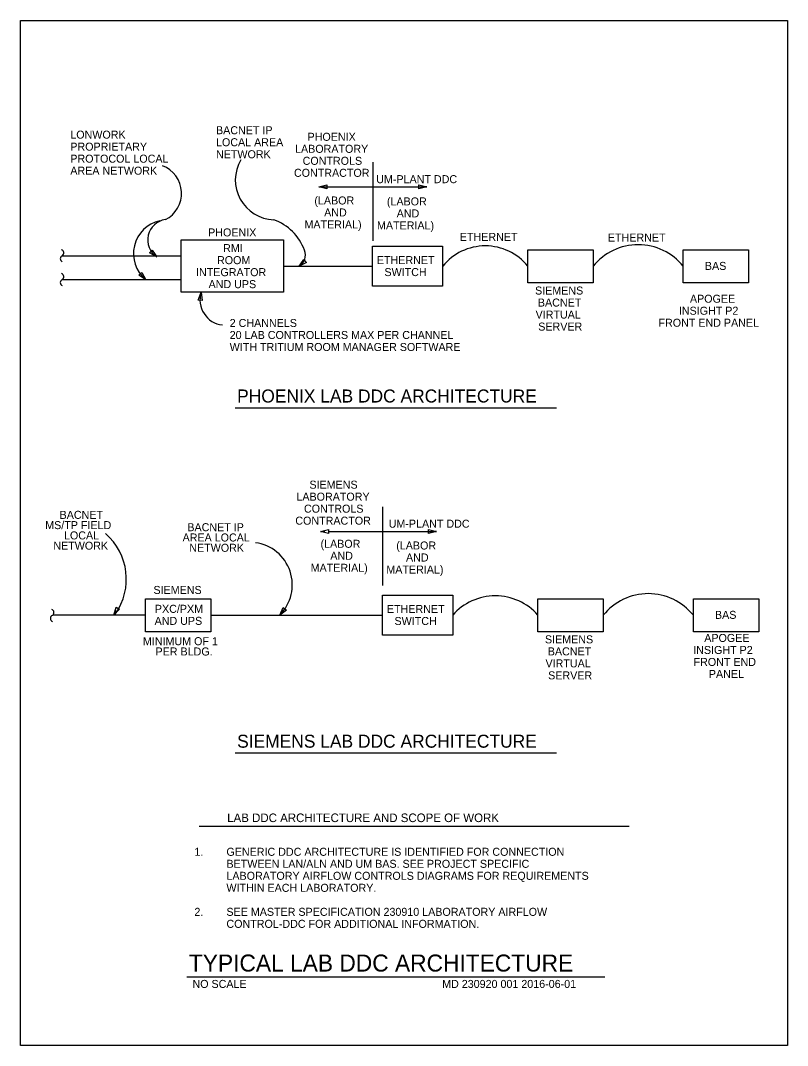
# Model space of a CAD drawing. Extents: x 10272.9 to 10336.8, y 10039.8 to 10125.2.
import ezdxf

# ---------------------------------------------------------------- set-up
doc = ezdxf.new("R2010")
doc.units = 0
for name, color, linetype in [('G-ANNO-CELL', 7, 'Continuous'), ('G-ANNO-TEXT', 7, 'Continuous'), ('G-DETL-LINE', 7, 'Continuous'), ('G-DETL-TEXT', 7, 'Continuous'), ('G-DETL-TTXT', 7, 'Continuous'), ('M-ANNO-NPLT', 7, 'Continuous'), ('M-EQPM', 7, 'Continuous')]:
    doc.layers.add(name, color=color, linetype=linetype)

msp = doc.modelspace()

# ---------------------------------------------------------------- linework, layer by layer
at = {"layer": 'G-ANNO-CELL'}
for p, q in [((10290.766, 10092.921), (10317.523, 10092.921)), ((10290.766, 10064.173), (10317.523, 10064.173)), ((10287.772, 10058.074), (10323.578, 10058.074))]:
    msp.add_line(p, q, dxfattribs=at)
at = {"layer": 'G-DETL-LINE'}
for p, q in [((10276.37, 10105.58), (10286.263, 10105.58)), ((10294.798, 10104.7), (10302.199, 10104.7)), ((10276.37, 10103.591), (10286.263, 10103.591)), ((10283.314, 10075.643), (10275.658, 10075.643)), ((10288.752, 10075.643), (10297.41, 10075.643)), ((10294.3, 10075.643), (10303.036, 10075.643))]:
    msp.add_line(p, q, dxfattribs=at)
for points in [[(10286.263, 10106.895), (10294.798, 10106.895), (10294.798, 10102.547), (10286.263, 10102.547)], [(10302.199, 10106.359), (10308.047, 10106.359), (10308.047, 10103.041), (10302.199, 10103.041)], [(10315.142, 10106.074), (10320.58, 10106.074), (10320.58, 10103.326), (10315.142, 10103.326)], [(10328.085, 10106.074), (10333.523, 10106.074), (10333.523, 10103.326), (10328.085, 10103.326)], [(10283.314, 10077.017), (10288.752, 10077.017), (10288.752, 10074.269), (10283.314, 10074.269)], [(10303.036, 10077.301), (10308.884, 10077.301), (10308.884, 10073.984), (10303.036, 10073.984)], [(10315.979, 10077.017), (10321.417, 10077.017), (10321.417, 10074.269), (10315.979, 10074.269)], [(10328.922, 10077.017), (10334.359, 10077.017), (10334.359, 10074.269), (10328.922, 10074.269)]]:
    msp.add_lwpolyline(points, close=True, dxfattribs=at)
for centre, radius, start, end in [((10276.227, 10105.814), 0.274, 301.55913, 71.51636), ((10311.595, 10101.833), 4.561, 38.93991, 141.06009), ((10324.332, 10101.668), 4.824, 38.93991, 141.06009), ((10276.474, 10105.33), 0.271, 112.5259, 247.4741), ((10276.227, 10103.825), 0.274, 301.55913, 71.51636), ((10276.474, 10103.341), 0.271, 112.5259, 247.4741), ((10312.431, 10072.53), 4.719, 41.26064, 138.73936), ((10325.169, 10072.61), 4.824, 38.93991, 141.06009), ((10275.411, 10075.858), 0.274, 301.55913, 71.51636), ((10275.659, 10075.375), 0.271, 112.5259, 247.4741)]:
    msp.add_arc(centre, radius, start, end, dxfattribs=at)
at = {"layer": 'G-DETL-TEXT'}
for p, q in [((10302.236, 10113.365), (10302.236, 10106.812)), ((10297.736, 10111.312), (10306.736, 10111.312)), ((10297.736, 10111.312), (10298.091, 10111.312)), ((10306.736, 10111.312), (10306.294, 10111.312)), ((10296.086, 10104.698), (10296.299, 10104.881)), ((10283.323, 10103.565), (10283.03, 10103.891)), ((10303.036, 10084.673), (10303.036, 10078.12)), ((10297.87, 10082.62), (10298.233, 10082.62)), ((10298.536, 10082.62), (10307.536, 10082.62)), ((10307.536, 10082.62), (10307.293, 10082.62)), ((10280.676, 10075.645), (10280.88, 10076.013)), ((10294.479, 10075.654), (10294.693, 10075.912))]:
    msp.add_line(p, q, dxfattribs=at)
for points in [[(10298.403, 10111.145), (10297.736, 10111.312), (10298.403, 10111.479)], [(10306.07, 10111.479), (10306.736, 10111.312), (10306.07, 10111.145)], [(10283.869, 10106.052), (10284.246, 10105.477), (10283.643, 10105.807)], [(10296.701, 10105.005), (10296.086, 10104.698), (10296.484, 10105.258)], [(10283.001, 10104.172), (10283.323, 10103.565), (10282.753, 10103.949)], [(10287.699, 10101.887), (10287.938, 10102.531), (10288.03, 10101.851)], [(10298.536, 10082.453), (10297.87, 10082.62), (10298.536, 10082.787)], [(10306.87, 10082.787), (10307.536, 10082.62), (10306.87, 10082.453)], [(10281.145, 10076.147), (10280.676, 10075.645), (10280.854, 10076.309)], [(10295.033, 10076.06), (10294.479, 10075.654), (10294.776, 10076.273)]]:
    msp.add_lwpolyline(points, close=True, dxfattribs=at)
for centre, radius, start, end in [((10294.11, 10111.892), 3.329, 149.90492, 267.86122), ((10283.849, 10110.774), 2.455, 296.84378, 69.20826), ((10285.096, 10105.758), 2.795, 102.39819, 230.62166), ((10285.198, 10106.894), 1.706, 98.08842, 236.10688), ((10292.589, 10104.596), 4.208, 20.03814, 70.62479), ((10295.555, 10105.627), 1.07, 299.77025, 22.59452), ((10289.936, 10101.893), 2.097, 162.28199, 263.65138), ((10276.69, 10078.643), 5.021, 324.6262, 49.2367), ((10291.983, 10078.169), 3.543, 314.77186, 82.3294)]:
    msp.add_arc(centre, radius, start, end, dxfattribs=at)
at = {"layer": 'G-DETL-TTXT'}
msp.add_line((10286.734, 10045.533), (10321.555, 10045.533), dxfattribs=at)
at = {"layer": 'M-ANNO-NPLT'}
msp.add_lwpolyline([(10272.898, 10125.166), (10336.758, 10125.166), (10336.758, 10039.806), (10272.898, 10039.806)], close=True, dxfattribs=at)

# ---------------------------------------------------------------- texts
at = {"layer": 'G-ANNO-CELL'}
for s, p in [('PHOENIX LAB DDC ARCHITECTURE', (10290.933, 10093.353)), ('SIEMENS LAB DDC ARCHITECTURE', (10290.933, 10064.606))]:
    msp.add_text(s, height=1.08333, dxfattribs=at).set_placement(p)
at = {"layer": 'G-ANNO-TEXT'}
for s, height, p in [('LONWORK ', 0.6667, (10277.044, 10115.326)), ('BACNET IP', 0.6667, (10289.176, 10115.694)), ('LOCAL AREA', 0.6667, (10289.176, 10114.694)), ('PROPRIETARY ', 0.66667, (10277.044, 10114.326)), ('NETWORK', 0.6667, (10289.176, 10113.694)), ('PROTOCOL LOCAL', 0.66667, (10277.044, 10113.326)), ('AREA NETWORK', 0.66667, (10277.044, 10112.326)), ('1.', 0.6667, (10287.377, 10055.604)), ('GENERIC DDC ARCHITECTURE IS IDENTIFIED FOR CONNECTION ', 0.66667, (10290.044, 10055.604)), ('BETWEEN LAN/ALN AND UM BAS. SEE PROJECT SPECIFIC ', 0.66667, (10290.044, 10054.604)), ('LABORATORY AIRFLOW CONTROLS DIAGRAMS FOR REQUIREMENTS ', 0.66667, (10290.044, 10053.604)), ('WITHIN EACH LABORATORY.', 0.66667, (10290.044, 10052.604)), ('2.', 0.6667, (10287.377, 10050.604)), ('SEE MASTER SPECIFICATION 230910 LABORATORY AIRFLOW ', 0.66667, (10290.044, 10050.604)), ('CONTROL-DDC FOR ADDITIONAL INFORMATION.', 0.66667, (10290.044, 10049.604))]:
    msp.add_text(s, height=height, dxfattribs=at).set_placement(p)
at = {"layer": 'G-DETL-LINE'}
for s, p in [('SIEMENS', (10283.969, 10077.41)), ('PXC/PXM', (10284.087, 10075.837)), ('AND UPS', (10284.063, 10074.837))]:
    msp.add_text(s, height=0.6667, dxfattribs=at).set_placement(p)
at = {"layer": 'G-DETL-TEXT'}
for s, height, p in [('PHOENIX', 0.6667, (10296.798, 10115.147)), ('LABORATORY ', 0.66667, (10295.757, 10114.147)), ('CONTROLS', 0.6667, (10296.387, 10113.147)), ('CONTRACTOR', 0.6667, (10295.666, 10112.147)), ('UM-PLANT DDC', 0.66667, (10302.515, 10111.619)), ('(LABOR', 0.6667, (10297.366, 10109.844)), ('(LABOR', 0.6667, (10303.404, 10109.766)), ('AND ', 0.6667, (10298.178, 10108.844)), ('AND ', 0.6667, (10304.216, 10108.766)), ('MATERIAL)', 0.6667, (10296.543, 10107.844)), ('MATERIAL)', 0.6667, (10302.58, 10107.766)), ('PHOENIX', 0.6667, (10288.521, 10107.185)), ('ETHERNET', 0.6667, (10309.474, 10106.815)), ('ETHERNET', 0.6667, (10321.805, 10106.759)), ('RMI', 0.6667, (10289.768, 10105.875)), ('ROOM ', 0.6667, (10289.261, 10104.875)), ('ETHERNET', 0.6667, (10302.569, 10104.881)), ('BAS', 0.6667, (10329.882, 10104.395)), ('INTEGRATOR', 0.6667, (10287.513, 10103.875)), ('SWITCH', 0.6667, (10303.201, 10103.881)), ('AND UPS', 0.6667, (10288.556, 10102.875)), ('SIEMENS ', 0.6667, (10315.74, 10102.343)), ('APOGEE ', 0.6667, (10328.635, 10101.662)), ('BACNET', 0.6667, (10315.975, 10101.343)), ('VIRTUAL', 0.6667, (10315.785, 10100.343)), ('INSIGHT P2 ', 0.66667, (10327.713, 10100.662)), ('2 CHANNELS', 0.6667, (10290.315, 10099.643)), ('SERVER', 0.6667, (10316.006, 10099.343)), ('FRONT END PANEL', 0.66667, (10326.017, 10099.662)), ('20 LAB CONTROLLERS MAX PER CHANNEL', 0.66667, (10290.315, 10098.643)), ('WITH TRITIUM ROOM MANAGER SOFTWARE', 0.66667, (10290.315, 10097.643)), ('SIEMENS', 0.6667, (10296.952, 10086.179)), ('LABORATORY ', 0.66667, (10295.87, 10085.179)), ('CONTROLS', 0.6667, (10296.5, 10084.179)), ('BACNET', 0.6667, (10276.153, 10083.665)), ('CONTRACTOR', 0.6667, (10295.779, 10083.179)), ('UM-PLANT DDC', 0.66667, (10303.554, 10082.927)), ('MS/TP FIELD', 0.66667, (10274.957, 10082.808)), ('BACNET IP', 0.6667, (10286.788, 10082.635)), ('LOCAL ', 0.6667, (10276.517, 10081.952)), ('AREA LOCAL', 0.6667, (10286.392, 10081.778)), ('(LABOR', 0.6667, (10297.878, 10081.254)), ('NETWORK', 0.6667, (10275.633, 10081.096)), ('NETWORK', 0.6667, (10286.951, 10080.922)), ('(LABOR', 0.6667, (10304.182, 10081.112)), ('AND ', 0.6667, (10298.69, 10080.254)), ('AND ', 0.6667, (10304.994, 10080.112)), ('MATERIAL)', 0.6667, (10297.055, 10079.254)), ('MATERIAL)', 0.6667, (10303.358, 10079.112)), ('ETHERNET', 0.6667, (10303.406, 10075.824)), ('BAS', 0.6667, (10330.719, 10075.337)), ('SWITCH', 0.6667, (10304.038, 10074.824)), ('MINIMUM OF 1', 0.66667, (10283.09, 10073.141)), ('SIEMENS ', 0.6667, (10316.565, 10073.295)), ('APOGEE ', 0.6667, (10329.829, 10073.413)), ('PER BLDG.', 0.6667, (10284.138, 10072.285)), ('BACNET', 0.6667, (10316.799, 10072.295)), ('INSIGHT P2 ', 0.66667, (10328.908, 10072.413)), ('VIRTUAL', 0.6667, (10316.61, 10071.295)), ('FRONT END ', 0.6667, (10328.937, 10071.413)), ('SERVER', 0.6667, (10316.831, 10070.295)), ('PANEL', 0.6667, (10330.211, 10070.413))]:
    msp.add_text(s, height=height, dxfattribs=at).set_placement(p)
at = {"layer": 'G-DETL-TTXT'}
for s, height, p in [('TYPICAL LAB DDC ARCHITECTURE', 1.41667, (10286.917, 10045.965)), ('NO SCALE', 0.6667, (10287.216, 10044.6)), ('MD 230920 001 2016-06-01', 0.66667, (10308.005, 10044.6))]:
    msp.add_text(s, height=height, dxfattribs=at).set_placement(p)
at = {"layer": 'M-EQPM'}
msp.add_text('LAB DDC ARCHITECTURE AND SCOPE OF WORK', height=0.715, dxfattribs=at).set_placement((10290.106, 10058.411))

doc.saveas('drawing.dxf')
